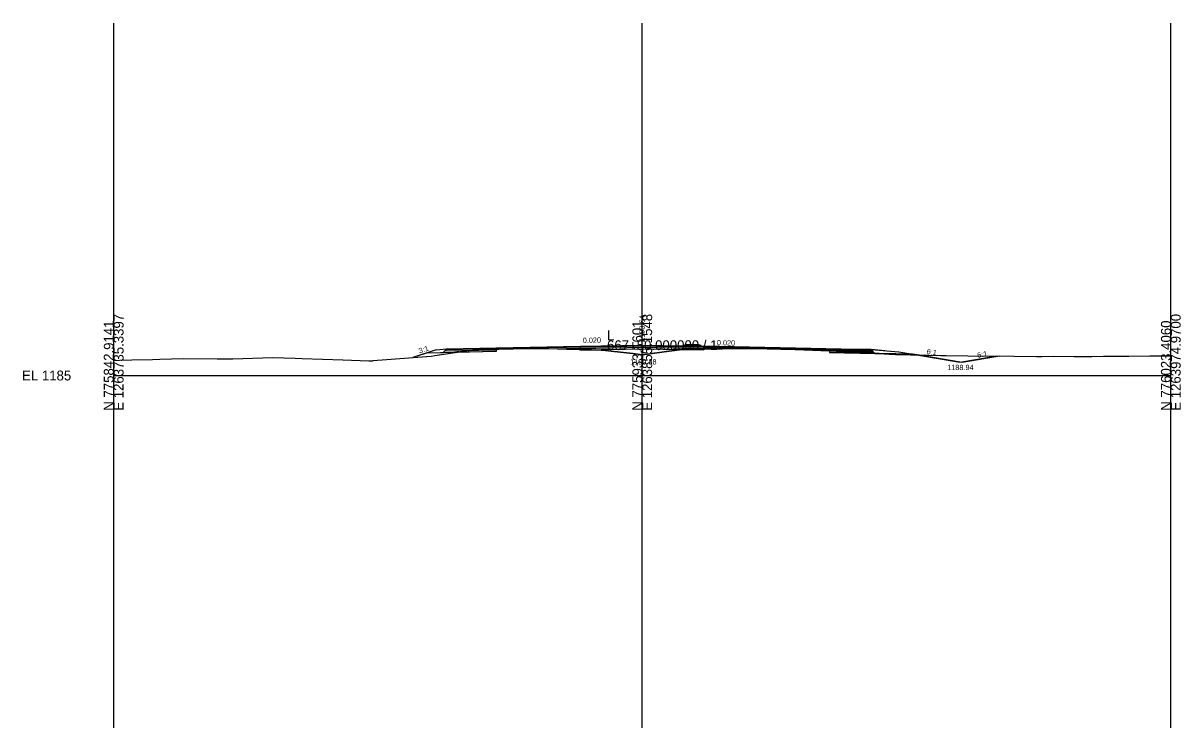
# Model space of a CAD drawing. Extents: x -41 to 1262860, y -100 to 777489.
# Drawn here: x -25.7 to 302.8, y 2225 to 2425 of the extents above; entities that cross this region are included whole.
import ezdxf

# ---------------------------------------------------------------- set-up
doc = ezdxf.new("R2010")
doc.units = 0
for name, color, linetype in [('Exist Cross Section Cell', 7, 'Continuous'), ('Exist XS Center Line Elevation Label', 7, 'Continuous'), ('Exist XS Ground Line', 7, 'Continuous'), ('Prop CMT Pvmt Course 1', 7, 'Continuous'), ('Prop CMT Pvmt Course 4', 7, 'Continuous'), ('Prop CMT Pvmt Surface', 7, 'Continuous'), ('Prop CMT Shld Paved Course 1', 7, 'Continuous'), ('Prop CMT Shld Paved Course 2', 7, 'Continuous'), ('Prop CMT Shld Paved Course 4', 7, 'Continuous'), ('Prop CMT Subgrade Earthwork', 7, 'Continuous'), ('Prop Conc Curb and Gutter', 7, 'Continuous'), ('Prop Conc Island Cover', 7, 'Continuous'), ('Prop XS Ditch Standard Text', 7, 'Continuous'), ('Prop XS Earthwork Shape', 7, 'Continuous'), ('Prop XS Exc Vertical Line 1', 7, 'Continuous'), ('Prop XS Exc Vertical Line 2', 7, 'Continuous'), ('Prop XS Exc Vertical Line 3', 7, 'Continuous'), ('Prop XS Finish Grade', 7, 'Continuous'), ('Prop XS Hydro Elevations', 7, 'Continuous'), ('Prop XS SE Text', 7, 'Continuous'), ('Prop XS Side Slope Text', 7, 'Continuous'), ('Scratch_Level_4', 7, 'Continuous'), ('Scratch_Level_6', 7, 'Continuous')]:
    doc.layers.add(name, color=color, linetype=linetype)

msp = doc.modelspace()

# ---------------------------------------------------------------- linework, layer by layer
at = {"layer": 'Exist Cross Section Cell'}
for p, q in [((150, 2325), (150, 2335)), ((0, 2325), (150, 2325)), ((150, 2325), (300, 2325))]:
    msp.add_line(p, q, dxfattribs=at)
at = {"layer": 'Exist XS Ground Line'}
msp.add_lwpolyline([(0, 2329.27), (1.63, 2329.35), (5.18, 2329.4), (11.06, 2329.51), (13.06, 2329.59), (19.69, 2329.84), (29.38, 2329.69), (31.53, 2329.69), (32.57, 2329.73), (33.84, 2329.76), (45.09, 2330.08), (51.53, 2329.91), (53.53, 2329.87), (65, 2329.45), (72.45, 2329.17), (73.45, 2329.17), (73.66, 2329.24), (90.14, 2330.48), (91.09, 2330.68), (96.9, 2331.56), (100.85, 2332.12), (102.64, 2332.26), (105.02, 2332.35), (107.78, 2332.47), (109.27, 2332.52), (110.7, 2332.6), (113.42, 2332.61), (123.46, 2332.64), (128.49, 2332.5), (135.57, 2332.31), (138.29, 2332.2), (138.83, 2332.18), (141.21, 2331.91), (147.28, 2331.27), (150.05, 2330.87), (155.56, 2331.61), (157.68, 2331.89), (161.34, 2332.36), (162.16, 2332.39), (164.64, 2332.48), (168.17, 2332.53), (177, 2332.67), (185.42, 2332.56), (189.35, 2332.51), (193.38, 2332.37), (203.09, 2332.03), (208.74, 2331.74), (215.71, 2331.36), (220.08, 2331.05), (221.88, 2330.98), (234.64, 2330.68), (236.27, 2330.64), (242.36, 2330.56), (255.47, 2330.44), (261.9, 2330.36), (263.39, 2330.4), (266.75, 2330.48), (272.5, 2330.43), (277.57, 2330.36), (280.85, 2330.44), (288.1, 2330.45), (294.08, 2330.57), (299.85, 2330.62), (300, 2330.63)], dxfattribs=at)
at = {"layer": 'Prop CMT Pvmt Course 1'}
for p, q in [((132.5, 2333.04), (150, 2333.39)), ((150, 2333.39), (167.49, 2333.04))]:
    msp.add_line(p, q, dxfattribs=at)
for points in [[(108.5, 2332.56), (108.5, 2332.81), (108.5, 2332.81), (132.5, 2333.29), (132.5, 2333.04), (132.5, 2333.04), (108.5, 2332.56), (108.5, 2332.56), (108.5, 2332.56)], [(210.82, 2332.17), (210.82, 2332.42), (167.5, 2333.29), (167.5, 2333.29), (167.5, 2333.04), (167.5, 2333.04), (167.5, 2333.04), (210.82, 2332.17), (210.82, 2332.17)]]:
    msp.add_lwpolyline(points, dxfattribs=at)
at = {"layer": 'Prop CMT Pvmt Course 4'}
for p, q in [((132.5, 2332.7), (132.5, 2332.25)), ((132.5, 2332.25), (150.02, 2332.6)), ((149.98, 2332.6), (167.48, 2332.25)), ((167.5, 2332.7), (167.5, 2332.25)), ((93.9, 2331.93), (93.44, 2331.46)), ((108.5, 2331.77), (93.44, 2331.46))]:
    msp.add_line(p, q, dxfattribs=at)
at = {"layer": 'Prop CMT Pvmt Surface'}
for p, q in [((94.5, 2332.53), (108.5, 2332.81)), ((108.5, 2332.81), (132.5, 2333.29)), ((132.5, 2333.29), (150, 2333.64)), ((150, 2333.64), (167.5, 2333.29)), ((167.5, 2333.29), (210.82, 2332.42)), ((210.82, 2332.42), (214.95, 2332.34))]:
    msp.add_line(p, q, dxfattribs=at)
at = {"layer": 'Prop CMT Shld Paved Course 1'}
for p, q in [((94.5, 2332.53), (108.5, 2332.81)), ((104.5, 2332.73), (104.5, 2332.73)), ((108.5, 2332.81), (108.5, 2332.56)), ((132.5, 2333.29), (150, 2333.64)), ((150, 2333.64), (167.5, 2333.29)), ((108.5, 2332.56), (94.24, 2332.27)), ((94.5, 2332.53), (94.24, 2332.27)), ((108.5, 2332.56), (108.5, 2332.56))]:
    msp.add_line(p, q, dxfattribs=at)
msp.add_lwpolyline([(210.82, 2332.42), (210.82, 2332.42), (210.82, 2332.17), (210.82, 2332.17), (210.82, 2332.17), (215.2, 2332.08), (214.95, 2332.34), (214.95, 2332.34), (210.82, 2332.42)], dxfattribs=at)
at = {"layer": 'Prop CMT Shld Paved Course 2'}
for p, q in [((110.7, 2332.6), (109.27, 2332.57)), ((109.27, 2332.52), (110.7, 2332.6)), ((113.42, 2332.66), (110.7, 2332.6)), ((110.7, 2332.6), (113.42, 2332.61)), ((110.7, 2332.6), (110.7, 2332.6)), ((110.7, 2332.6), (110.7, 2332.6)), ((123.46, 2332.86), (113.42, 2332.66)), ((113.42, 2332.66), (113.42, 2332.66)), ((113.42, 2332.61), (123.46, 2332.64)), ((113.42, 2332.61), (113.42, 2332.61)), ((128.49, 2332.96), (123.46, 2332.86)), ((123.46, 2332.86), (123.46, 2332.86)), ((123.46, 2332.86), (123.46, 2332.86)), ((123.46, 2332.64), (123.46, 2332.64)), ((123.46, 2332.64), (123.46, 2332.64)), ((123.46, 2332.64), (125.9, 2332.57)), ((125.9, 2332.57), (128.49, 2332.62)), ((132.5, 2333.04), (128.49, 2332.96)), ((128.49, 2332.96), (128.49, 2332.96)), ((128.49, 2332.62), (132.5, 2332.7)), ((128.49, 2332.62), (128.49, 2332.62)), ((132.5, 2332.7), (150, 2333.05)), ((132.5, 2332.7), (132.5, 2333.04)), ((132.5, 2332.7), (132.5, 2332.7)), ((150, 2333.05), (167.5, 2332.7)), ((167.5, 2332.7), (167.5, 2333.04)), ((167.5, 2333.04), (168.17, 2333.02)), ((168.17, 2332.69), (167.5, 2332.7)), ((167.5, 2332.7), (167.5, 2332.7)), ((168.17, 2333.02), (168.17, 2333.02)), ((168.17, 2333.02), (177, 2332.85)), ((172.71, 2332.6), (168.17, 2332.69)), ((168.17, 2332.69), (168.17, 2332.69)), ((177, 2332.67), (172.71, 2332.6)), ((172.71, 2332.6), (172.71, 2332.6)), ((177, 2332.85), (185.42, 2332.68)), ((185.42, 2332.56), (177, 2332.67)), ((185.42, 2332.68), (185.42, 2332.68)), ((185.42, 2332.68), (189.35, 2332.6)), ((189.35, 2332.6), (189.35, 2332.6)), ((189.35, 2332.6), (193.38, 2332.52)), ((93.9, 2331.93), (94.24, 2332.27)), ((108.5, 2332.22), (93.9, 2331.93)), ((103.9, 2332.13), (103.9, 2332.13)), ((103.9, 2332.13), (103.9, 2332.13)), ((109.27, 2332.57), (108.5, 2332.56)), ((108.5, 2332.56), (108.5, 2332.22)), ((108.5, 2332.56), (108.5, 2332.49)), ((108.5, 2332.49), (109.27, 2332.52)), ((108.5, 2332.49), (108.5, 2332.49)), ((108.5, 2332.22), (108.5, 2332.22)), ((109.27, 2332.57), (109.27, 2332.57)), ((109.27, 2332.57), (109.27, 2332.57)), ((109.27, 2332.52), (109.27, 2332.52)), ((109.27, 2332.52), (109.27, 2332.52)), ((125.9, 2332.57), (125.9, 2332.57)), ((189.35, 2332.51), (185.42, 2332.56)), ((185.42, 2332.56), (185.42, 2332.56)), ((193.38, 2332.37), (189.35, 2332.51)), ((189.35, 2332.51), (189.35, 2332.51)), ((193.38, 2332.52), (193.38, 2332.52)), ((193.38, 2332.52), (193.38, 2332.52)), ((193.38, 2332.52), (203.09, 2332.33)), ((203.09, 2332.03), (193.38, 2332.37)), ((193.38, 2332.37), (193.38, 2332.37)), ((193.38, 2332.37), (193.38, 2332.37)), ((203.09, 2332.33), (203.09, 2332.33)), ((203.09, 2332.33), (208.74, 2332.21)), ((203.09, 2331.99), (203.09, 2332.03)), ((203.09, 2332.03), (203.09, 2332.03)), ((208.74, 2331.88), (203.09, 2331.99)), ((208.74, 2332.21), (210.82, 2332.17)), ((210.82, 2331.84), (208.74, 2331.88)), ((210.82, 2332.17), (210.82, 2331.84)), ((210.82, 2331.84), (210.82, 2331.84))]:
    msp.add_line(p, q, dxfattribs=at)
msp.add_lwpolyline([(210.82, 2332.17), (210.82, 2332.17), (210.82, 2331.84), (210.82, 2331.84), (210.82, 2331.84), (215.54, 2331.74), (215.2, 2332.08), (215.2, 2332.08), (210.82, 2332.17)], dxfattribs=at)
at = {"layer": 'Prop CMT Shld Paved Course 4'}
for p, q in [((168.17, 2332.53), (172.71, 2332.6)), ((97.4, 2332), (97.9, 2332.01)), ((103.9, 2332.13), (103.9, 2332.13)), ((108.5, 2332.22), (108.5, 2331.77)), ((128.49, 2332.5), (125.9, 2332.57)), ((128.49, 2332.5), (132.5, 2332.39)), ((168.17, 2332.53), (167.5, 2332.52)), ((203.09, 2331.99), (203.09, 2331.53)), ((216.01, 2331.28), (203.09, 2331.53)), ((210.82, 2331.84), (210.82, 2331.84)), ((215.54, 2331.74), (210.82, 2331.84)), ((210.82, 2331.84), (210.82, 2331.38)), ((215.54, 2331.74), (215.54, 2331.74)), ((215.54, 2331.74), (216.01, 2331.28))]:
    msp.add_line(p, q, dxfattribs=at)
at = {"layer": 'Prop CMT Subgrade Earthwork'}
for p, q in [((132.5, 2332.25), (150, 2332.6)), ((150, 2332.6), (167.5, 2332.25)), ((108.5, 2331.77), (88.75, 2331.37)), ((108.5, 2331.77), (108.5, 2332.49)), ((132.5, 2332.39), (132.5, 2332.25)), ((167.5, 2332.25), (167.5, 2332.52)), ((203.09, 2332.03), (203.09, 2331.53)), ((203.09, 2331.53), (226.7, 2331.06))]:
    msp.add_line(p, q, dxfattribs=at)
at = {"layer": 'Prop Conc Curb and Gutter'}
for p, q in [((161.66, 2333.4), (161.67, 2333.57)), ((161.66, 2333.4), (161.66, 2333.4)), ((161.66, 2333.4), (161.66, 2333.28)), ((163.42, 2333.4), (161.66, 2333.4)), ((161.66, 2333.4), (161.66, 2333.4)), ((161.66, 2333.28), (161.66, 2333.28)), ((161.66, 2333.28), (163.42, 2333.28)), ((161.67, 2333.57), (162.42, 2333.82)), ((161.67, 2333.57), (161.67, 2333.57)), ((162.42, 2333.82), (163.42, 2333.84)), ((162.42, 2333.82), (162.42, 2333.82)), ((163.42, 2333.84), (163.42, 2333.4)), ((163.42, 2333.28), (163.42, 2333.4)), ((163.42, 2333.4), (163.42, 2333.4)), ((163.42, 2333.28), (163.42, 2333.28)), ((163.42, 2333.28), (163.42, 2333.28)), ((165.99, 2333.72), (164.99, 2333.74)), ((164.99, 2333.74), (164.99, 2333.3)), ((166.75, 2333.3), (164.99, 2333.3)), ((164.99, 2333.3), (164.99, 2333.18)), ((164.99, 2333.3), (164.99, 2333.3)), ((164.99, 2333.18), (164.99, 2333.18)), ((164.99, 2333.18), (166.75, 2333.18)), ((166.74, 2333.47), (165.99, 2333.72)), ((165.99, 2333.72), (165.99, 2333.72)), ((166.75, 2333.3), (166.74, 2333.47)), ((166.74, 2333.47), (166.74, 2333.47)), ((166.75, 2333.18), (166.75, 2333.3)), ((166.75, 2333.3), (166.75, 2333.3)), ((166.75, 2333.3), (166.75, 2333.3)), ((166.75, 2333.18), (166.75, 2333.18)), ((166.75, 2333.18), (166.75, 2333.18))]:
    msp.add_line(p, q, dxfattribs=at)
at = {"layer": 'Prop Conc Island Cover'}
for p, q in [((163.42, 2333.84), (163.42, 2333.59)), ((164.99, 2333.74), (163.42, 2333.84)), ((164.99, 2333.49), (163.42, 2333.59)), ((164.99, 2333.49), (164.99, 2333.74)), ((164.99, 2333.74), (164.99, 2333.74)), ((164.99, 2333.49), (164.99, 2333.49))]:
    msp.add_line(p, q, dxfattribs=at)
at = {"layer": 'Prop XS Earthwork Shape'}
for points in [[(135.53, 2332.31), (150, 2332.6), (161.56, 2332.36), (161.34, 2332.36), (157.68, 2331.89), (155.56, 2331.61), (150.05, 2330.87), (147.28, 2331.27), (141.21, 2331.91), (138.83, 2332.18), (138.29, 2332.2), (135.57, 2332.31)], [(90.14, 2330.48), (91.09, 2330.68), (96.69, 2331.53), (93.44, 2331.46), (88.75, 2331.37), (84.88, 2330.08)], [(96.9, 2331.56), (100.85, 2332.12), (102.64, 2332.26), (105.02, 2332.35), (107.78, 2332.47), (108.5, 2332.49), (108.5, 2331.77), (96.69, 2331.53)], [(132.5, 2332.39), (132.5, 2332.25), (135.53, 2332.31)], [(161.56, 2332.36), (167.5, 2332.25), (167.5, 2332.52), (164.64, 2332.48), (162.16, 2332.39)], [(203.09, 2331.53), (216.01, 2331.28), (215.94, 2331.35), (215.71, 2331.36), (208.74, 2331.74), (203.09, 2332.03)], [(216.01, 2331.28), (217.26, 2331.25), (215.94, 2331.35)], [(221.88, 2330.98), (228.05, 2330.84), (226.7, 2331.06), (217.26, 2331.25), (220.08, 2331.05)], [(228.05, 2330.84), (234.64, 2330.68), (236.27, 2330.64), (242.36, 2330.56), (251.45, 2330.48), (240.82, 2328.71)]]:
    msp.add_lwpolyline(points, close=True, dxfattribs=at)
at = {"layer": 'Prop XS Exc Vertical Line 1'}
msp.add_line((0, 2225), (0, 2425), dxfattribs=at)
at = {"layer": 'Prop XS Exc Vertical Line 2'}
msp.add_line((150, 2225), (150, 2425), dxfattribs=at)
at = {"layer": 'Prop XS Exc Vertical Line 3'}
msp.add_line((300, 2225), (300, 2425), dxfattribs=at)
at = {"layer": 'Prop XS Finish Grade'}
for p, q in [((91.5, 2332.29), (84.88, 2330.08)), ((91.5, 2332.29), (94.5, 2332.53)), ((93.44, 2331.46), (94.5, 2332.53)), ((214.95, 2332.34), (222.82, 2331.71)), ((214.95, 2332.34), (216.01, 2331.28)), ((222.82, 2331.71), (240.13, 2328.82)), ((240.13, 2328.82), (250.13, 2330.49))]:
    msp.add_line(p, q, dxfattribs=at)
msp.add_lwpolyline([(218.82, 2332.03), (214.95, 2332.34), (214.95, 2332.34)], dxfattribs=at)
at = {"layer": 'Scratch_Level_4'}
msp.add_line((300, 2225), (300, 2425), dxfattribs=at)
at = {"layer": 'Scratch_Level_6'}
msp.add_line((0, 2225), (0, 2425), dxfattribs=at)

# ---------------------------------------------------------------- texts
at = {"layer": 'Exist Cross Section Cell'}
for s, p in [('N 775842.9141', (0, 2315)), ('E 1263735.3397', (2.8, 2315)), ('N 775933.1601', (150, 2315)), ('E 1263855.1548', (152.8, 2315)), ('N 776023.4060', (300, 2315)), ('E 1263974.9700', (302.8, 2315))]:
    msp.add_text(s, height=2.8, rotation=90, dxfattribs=at).set_placement(p)
for s, p in [('L', (140, 2335)), ('667+50.000000 / 1', (140, 2332.2)), ('EL 1185', (-26, 2323.6))]:
    msp.add_text(s, height=2.8, dxfattribs=at).set_placement(p)
at = {"layer": 'Exist XS Center Line Elevation Label'}
msp.add_text('1190.88', height=1.5, dxfattribs=at).set_placement((146.56, 2328.13))
at = {"layer": 'Prop XS Ditch Standard Text'}
msp.add_text('1188.94', height=1.5, dxfattribs=at).set_placement((236.54, 2326.53))
at = {"layer": 'Prop XS Hydro Elevations'}
msp.add_text('1193.64', height=1.5, rotation=90, dxfattribs=at).set_placement((150.65, 2334.57))
at = {"layer": 'Prop XS SE Text'}
for rotation, p in [(1.1458, (133.13, 2334.21)), (358.8542, (171.16, 2333.58))]:
    msp.add_text('0.020', height=1.5, rotation=rotation, dxfattribs=at).set_placement(p)
at = {"layer": 'Prop XS Side Slope Text'}
for s, rotation, p in [('3:1', 18.4349, (86.81, 2331.2)), ('6:1', 350.5377, (230.63, 2331.15)), ('6:1', 9.4809, (245.18, 2330.02))]:
    msp.add_text(s, height=1.5, rotation=rotation, dxfattribs=at).set_placement(p)

doc.saveas('drawing.dxf')
